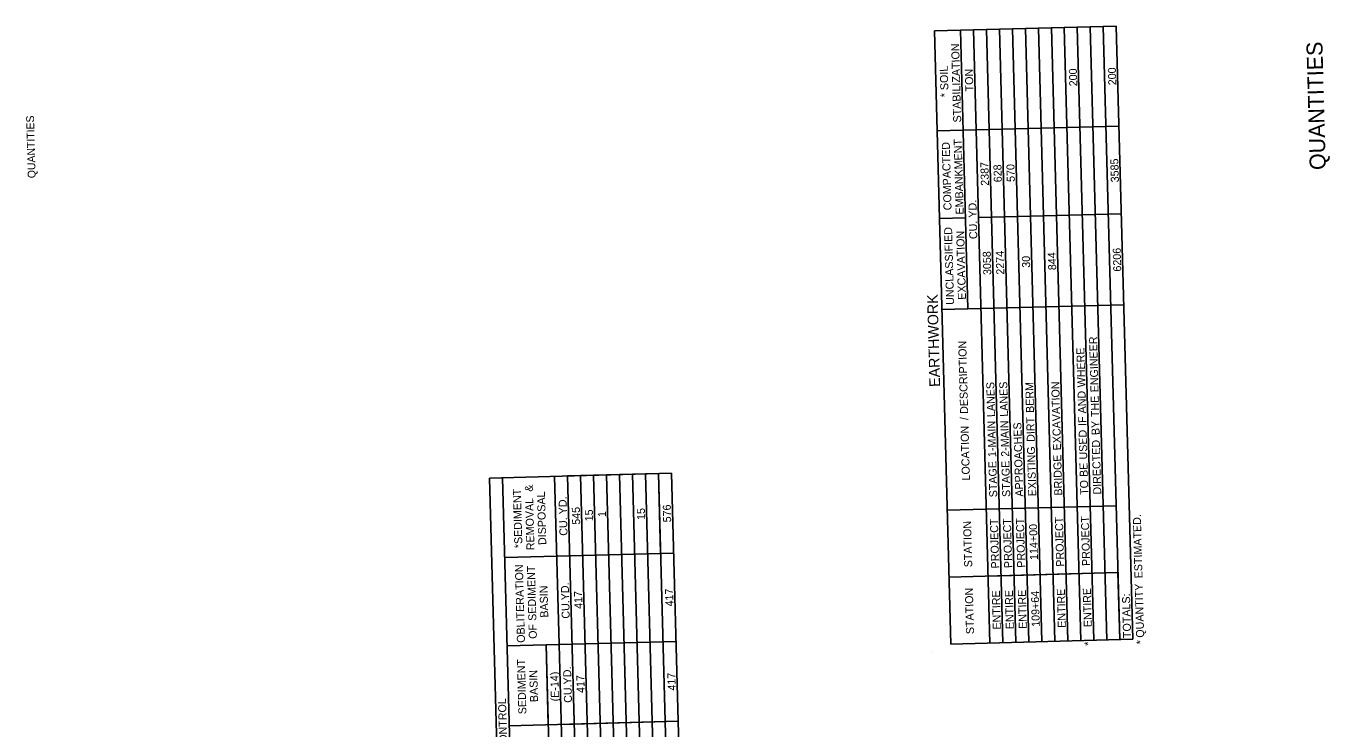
# Model space of a CAD drawing. Extents: x 1930078 to 1931323, y 596452 to 607874.
# Drawn here: x 1930226 to 1931204, y 602465 to 602992 of the extents above; entities that cross this region are included whole.
import ezdxf

# ---------------------------------------------------------------- set-up
doc = ezdxf.new("R2010")
doc.units = 0
for name, color, linetype in [('Default', 7, 'Continuous'), ('R_Border', 7, 'Continuous'), ('R_Border Prem', 7, 'Continuous')]:
    doc.layers.add(name, color=color, linetype=linetype)

msp = doc.modelspace()

# ---------------------------------------------------------------- linework, layer by layer
at = {"layer": 'Default'}
for p, q in [((1931043.58, 602991.91), (1930907.13, 602988.25)), ((1931043.58, 602991.91), (1930907.13, 602988.25)), ((1930919.48, 602528.21), (1930907.13, 602988.25)), ((1930932.23, 602779.71), (1930926.62, 602988.77)), ((1930948.72, 602529), (1930936.37, 602989.03)), ((1930958.46, 602529.26), (1930946.11, 602989.29)), ((1930968.21, 602529.52), (1930955.86, 602989.56)), ((1930977.96, 602529.78), (1930965.61, 602989.82)), ((1930987.7, 602530.04), (1930975.35, 602990.08)), ((1930997.45, 602530.31), (1930985.1, 602990.34)), ((1931007.2, 602530.57), (1930994.85, 602990.6)), ((1931016.94, 602530.83), (1931004.59, 602990.86)), ((1931026.69, 602531.09), (1931014.34, 602991.13)), ((1931036.43, 602531.35), (1931024.09, 602991.39)), ((1931046.18, 602531.61), (1931033.83, 602991.65)), ((1931055.93, 602531.88), (1931043.58, 602991.91)), ((1931045.59, 602916.86), (1930909.14, 602913.2)), ((1930930.4, 602847.93), (1930910.91, 602847.41)), ((1931047.36, 602851.07), (1930940.15, 602848.2)), ((1931049.19, 602782.85), (1930912.74, 602779.18)), ((1931039.44, 602782.59), (1930941.98, 602779.97)), ((1930709.99, 602656.45), (1930573.54, 602652.78)), ((1930605.63, 601457.38), (1930573.54, 602652.78)), ((1930606.39, 601792.43), (1930583.29, 602653.05)), ((1930625.66, 602527.88), (1930622.28, 602654.09)), ((1930700.25, 602656.19), (1930632.02, 602654.35)), ((1930664.11, 601458.95), (1930632.02, 602654.35)), ((1930673.86, 601459.21), (1930641.77, 602654.62)), ((1930683.6, 601459.47), (1930651.52, 602654.88)), ((1930693.35, 601459.73), (1930661.26, 602655.14)), ((1930703.1, 601459.99), (1930671.01, 602655.4)), ((1930712.84, 601460.26), (1930680.75, 602655.66)), ((1930722.59, 601460.52), (1930690.5, 602655.92)), ((1930708.35, 602354.53), (1930700.25, 602656.19)), ((1930701.86, 602596.24), (1930700.25, 602656.19)), ((1930742.08, 601461.04), (1930709.99, 602656.45)), ((1931043.49, 602632), (1930916.78, 602628.6)), ((1931043.49, 602632), (1930946.02, 602629.39)), ((1930711.6, 602596.51), (1930584.9, 602593.11)), ((1930711.6, 602596.51), (1930623.88, 602594.15)), ((1931044.83, 602581.81), (1930918.13, 602578.41)), ((1931044.83, 602581.81), (1930947.37, 602579.19)), ((1931046.18, 602531.61), (1931044.83, 602581.81)), ((1930713.38, 602530.23), (1930586.68, 602526.83)), ((1930622.28, 602290.77), (1930615.92, 602527.61)), ((1930617.53, 602467.67), (1930615.92, 602527.61)), ((1930713.38, 602530.23), (1930625.66, 602527.88)), ((1930645.38, 601793.48), (1930625.66, 602527.88)), ((1931055.93, 602531.88), (1930919.48, 602528.21)), ((1931055.93, 602531.88), (1930919.48, 602528.21)), ((1930714.99, 602470.29), (1930588.29, 602466.89)), ((1930714.99, 602470.29), (1930627.27, 602467.93))]:
    msp.add_line(p, q, dxfattribs=at)
at = {"layer": 'R_Border'}
msp.add_line((1930905.99, 602522), (1930905.99, 602522), dxfattribs=at)

# ---------------------------------------------------------------- texts
at = {"layer": 'Default'}
for s, height, p in [('STABILIZATION', 6, (1930927.28, 602919.66)), (' SOIL', 6, (1930917.68, 602941.7)), ('TON', 6, (1930936.4, 602942.97)), ('200', 6, (1931014.33, 602946.78)), ('200', 6, (1931043.57, 602947.57)), ('*', 6, (1930917.76, 602938.62)), ('EMBANKMENT', 6, (1930929.13, 602850.62)), ('COMPACTED', 6, (1930920.04, 602853.76)), ('2387', 6, (1930948.06, 602872.19)), ('628', 6, (1930957.74, 602874.78)), ('570', 6, (1930967.49, 602875.06)), ('3585', 6, (1931045.52, 602874.74)), (' YD.', 6, (1930939.01, 602846.01)), ('UNCLASSIFIED', 6, (1930921.95, 602782.79)), ('CU.', 6, (1930939.38, 602832.16)), ('EXCAVATION', 6, (1930930.85, 602786.65)), ('3058', 6, (1930949.86, 602805.18)), ('2274', 6, (1930959.6, 602805.46)), ('30', 6, (1930978.97, 602810.64)), ('844', 6, (1930998.52, 602808.84)), ('6206', 6, (1931047.32, 602807.76)), ('EARTHWORK', 8, (1930911.47, 602721.23)), (' DESCRIPTION', 6, (1930932.53, 602698.78)), (' WHERE', 6, (1931020.45, 602718.68)), (' ENGINEER', 6, (1931030.31, 602714.96)), (' LANES', 6, (1930952.78, 602696.39)), (' LANES', 6, (1930962.52, 602696.65)), (' BERM', 6, (1930981.95, 602699.48)), (' EXCAVATION', 6, (1931002.21, 602671.38)), (' AND', 6, (1931020.98, 602699.1)), (' THE', 6, (1931030.81, 602696.32)), (' /', 6, (1930932.65, 602694.11)), ('LOCATION', 6, (1930933.81, 602651.02)), (' 1-MAIN', 6, (1930953.58, 602666.35)), (' 2-MAIN', 6, (1930963.33, 602666.61)), ('APPROACHES', 6, (1930973.83, 602638.91)), (' DIRT', 6, (1930982.54, 602677.77)), (' IF', 6, (1931021.23, 602689.71)), (' BY', 6, (1931031.17, 602682.87)), (' USED', 6, (1931021.91, 602664.54)), ('EXISTING', 6, (1930983.57, 602639.17)), ('DIRECTED', 6, (1931032.3, 602640.48)), ('STAGE', 6, (1930954.33, 602638.39)), ('STAGE', 6, (1930964.08, 602638.65)), ('BRIDGE', 6, (1931003.07, 602639.7)), (' BE', 6, (1931022.26, 602651.48)), ('*SEDIMENT', 6, (1930598.21, 602600.24)), (' &', 6, (1930606.14, 602640.39)), ('DISPOSAL', 6, (1930616.15, 602602.62)), ('TO', 6, (1931022.56, 602640.22)), ('REMOVAL', 6, (1930607.26, 602598.73)), (' YD.', 6, (1930631.65, 602623.42)), ('576', 6, (1930709.78, 602619.61)), ('545', 6, (1930641.56, 602617.79)), ('15', 6, (1930651.24, 602620.38)), ('1', 6, (1930660.91, 602623.58)), ('15', 6, (1930690.23, 602621.43)), ('PROJECT', 6, (1931004.5, 602586.35)), ('PROJECT', 6, (1931023.99, 602586.88)), (' ESTIMATED.', 6, (1931063.31, 602575.39)), ('CU.', 6, (1930632.02, 602609.56)), ('STATION', 6, (1930935.56, 602585.92)), ('PROJECT', 6, (1930955.76, 602585.04)), ('PROJECT', 6, (1930965.51, 602585.31)), ('PROJECT', 6, (1930975.26, 602585.57)), ('114+00', 6, (1930984.85, 602591.41)), ('OBLITERATION', 6, (1930600.12, 602529.24)), (' SEDIMENT', 6, (1930608.74, 602543.47)), ('BASIN', 6, (1930617.62, 602548.11)), ('CU.YD.', 6, (1930633.69, 602547.33)), ('417', 6, (1930643.25, 602554.71)), ('417', 6, (1930711.48, 602556.53)), ('STATION', 6, (1930936.91, 602535.73)), ('ENTIRE', 6, (1930957, 602539.18)), ('ENTIRE', 6, (1930966.74, 602539.44)), ('ENTIRE', 6, (1930976.49, 602539.7)), ('109+64', 6, (1930986.2, 602541.22)), ('ENTIRE', 6, (1931005.73, 602540.49)), ('ENTIRE', 6, (1931025.22, 602541.01)), ('TOTALS:', 6, (1931054.7, 602532.82)), ('QUANTITY', 6, (1931064.45, 602533.08)), ('OF', 6, (1930609.04, 602532.22)), ('*', 6, (1931025.59, 602527.12)), ('*', 6, (1931064.58, 602528.16)), ('SEDIMENT', 6, (1930601.18, 602475.64)), ('BASIN', 6, (1930609.94, 602484.75)), ('(E-14)', 6, (1930625.61, 602485.29)), ('CU.YD.', 6, (1930635.39, 602484.22)), ('417', 6, (1930713.17, 602493.43)), ('417', 6, (1930644.94, 602491.6)), (' CONTROL', 6, (1930586.97, 602446.19))]:
    msp.add_text(s, height=height, rotation=91.53769, dxfattribs=at).set_placement(p)
at = {"layer": 'R_Border'}
msp.add_text('QUANTITIES', height=12, rotation=91.53769, dxfattribs=at).set_placement((1931200.69, 602884.08))
at = {"layer": 'R_Border Prem'}
msp.add_text('QUANTITIES', height=5.862, rotation=91.53769, dxfattribs=at).set_placement((1930233.13, 602877.83))

doc.saveas('drawing.dxf')
